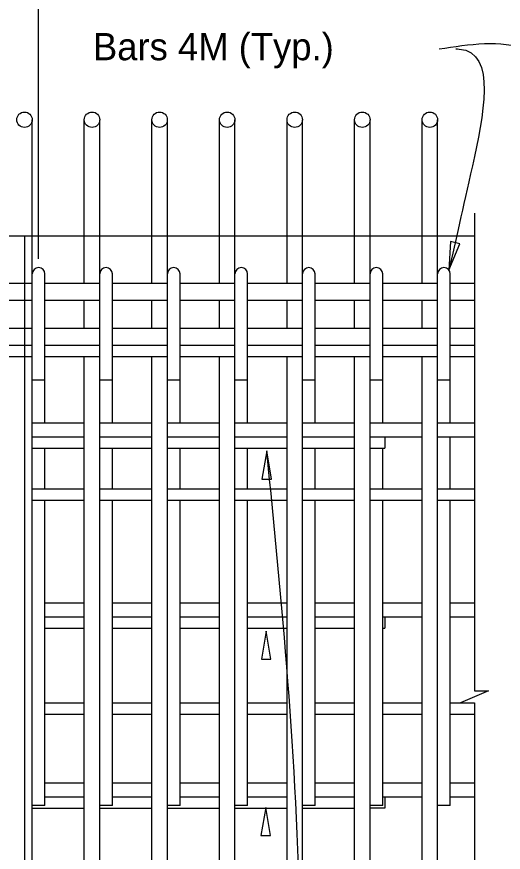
# Model space of a CAD drawing. Extents: x 120735 to 120771, y 120670.1 to 120685.4.
# Drawn here: x 120749.57 to 120751.37, y 120679.138 to 120682.233 of the extents above; entities that cross this region are included whole.
import ezdxf

# ---------------------------------------------------------------- set-up
doc = ezdxf.new("R2010")
doc.units = 0
for name, color, linetype in [('BeamConc', 7, 'Continuous'), ('BeamConc_h', 7, 'Continuous'), ('Dimension', 7, 'Continuous'), ('Rebar', 7, 'Continuous'), ('TextStructures', 7, 'Continuous')]:
    doc.layers.add(name, color=color, linetype=linetype)

msp = doc.modelspace()

# ---------------------------------------------------------------- linework, layer by layer
at = {"layer": 'BeamConc'}
msp.add_line((120747.5987, 120681.4214), (120751.2636, 120681.4214), dxfattribs=at)
at = {"layer": 'BeamConc_h'}
msp.add_line((120749.5987, 120681.4214), (120749.5987, 120677.1815), dxfattribs=at)
at = {"layer": 'Dimension'}
msp.add_line((120749.6508, 120681.3364), (120749.6508, 120682.5406), dxfattribs=at)
msp.add_lwpolyline([(120751.2636, 120681.5047), (120751.2636, 120679.7363), (120751.3153, 120679.7363), (120751.212, 120679.6913), (120751.2636, 120679.6913), (120751.2636, 120678.0689), (120751.3153, 120678.0689), (120751.212, 120678.0239), (120751.2636, 120678.0239), (120751.2636, 120676.083)], dxfattribs=at)
for points in [[(120751.1693, 120681.2943), (120751.2093, 120681.3921), (120751.1748, 120681.3998)], [(120750.4952, 120680.6245), (120750.4773, 120680.5205), (120750.5125, 120680.5204)], [(120750.4932, 120679.9578), (120750.4753, 120679.8537), (120750.5106, 120679.8536)], [(120750.4912, 120679.3042), (120750.4732, 120679.2001), (120750.5085, 120679.2)]]:
    msp.add_lwpolyline(points, close=True, dxfattribs=at)
for points in [[(120751.1329, 120682.1134), (120751.458, 120682.1121), (120751.7391, 120681.7555), (120751.672, 120681.2899)], [(120751.1944, 120682.1134), (120751.2076, 120682.1129), (120751.2559, 120681.6807), (120751.1692, 120681.2943)], [(120750.6698, 120675.9492), (120750.5712, 120675.9492), (120750.4797, 120676.5019), (120750.4952, 120680.6245)]]:
    msp.add_spline(points, degree=3, dxfattribs=at)
at = {"layer": 'Rebar'}
for p, q in [((120749.6274, 120676.3667), (120749.6274, 120681.851)), ((120749.8201, 120681.246), (120749.8201, 120681.851)), ((120749.8774, 120676.3667), (120749.8774, 120681.851)), ((120750.0701, 120681.246), (120750.0701, 120681.851)), ((120750.1274, 120676.3667), (120750.1274, 120681.851)), ((120750.3201, 120681.246), (120750.3201, 120681.851)), ((120750.3774, 120676.3667), (120750.3774, 120681.851)), ((120750.5701, 120681.246), (120750.5701, 120681.851)), ((120750.6274, 120676.3667), (120750.6274, 120681.851)), ((120750.8201, 120681.246), (120750.8201, 120681.851)), ((120750.8774, 120676.3667), (120750.8774, 120681.851)), ((120751.0701, 120681.246), (120751.0701, 120681.851)), ((120751.1274, 120676.3667), (120751.1274, 120681.851)), ((120749.6742, 120680.7287), (120749.6742, 120681.2799)), ((120749.9242, 120680.7287), (120749.9242, 120681.2799)), ((120750.1742, 120680.7287), (120750.1742, 120681.2799)), ((120750.4242, 120680.7287), (120750.4242, 120681.2799)), ((120750.6742, 120680.7287), (120750.6742, 120681.2799)), ((120750.9242, 120680.7287), (120750.9242, 120681.2799)), ((120751.1742, 120680.7287), (120751.1742, 120681.2799)), ((120749.3201, 120681.246), (120749.6274, 120681.246)), ((120749.6742, 120681.246), (120749.8774, 120681.246)), ((120749.9242, 120681.246), (120750.1274, 120681.246)), ((120750.1742, 120681.246), (120750.3774, 120681.246)), ((120750.4242, 120681.246), (120750.6274, 120681.246)), ((120750.6742, 120681.246), (120750.8774, 120681.246)), ((120750.9242, 120681.246), (120751.1274, 120681.246)), ((120751.1742, 120681.246), (120751.2636, 120681.246)), ((120749.3201, 120681.1835), (120749.6274, 120681.1835)), ((120749.6742, 120681.1835), (120749.8774, 120681.1835)), ((120749.8201, 120681.0788), (120749.8201, 120681.1835)), ((120749.9242, 120681.1835), (120750.1274, 120681.1835)), ((120750.0701, 120681.0788), (120750.0701, 120681.1835)), ((120750.1742, 120681.1835), (120750.3774, 120681.1835)), ((120750.3201, 120681.0788), (120750.3201, 120681.1835)), ((120750.4242, 120681.1835), (120750.6274, 120681.1835)), ((120750.5701, 120681.0788), (120750.5701, 120681.1835)), ((120750.6742, 120681.1835), (120750.8774, 120681.1835)), ((120750.8201, 120681.0788), (120750.8201, 120681.1835)), ((120750.9242, 120681.1835), (120751.1274, 120681.1835)), ((120751.0701, 120681.0788), (120751.0701, 120681.1835)), ((120751.1742, 120681.1835), (120751.2636, 120681.1835)), ((120749.3201, 120681.0788), (120749.6274, 120681.0788)), ((120749.6742, 120681.0788), (120749.8774, 120681.0788)), ((120749.9242, 120681.0788), (120750.1274, 120681.0788)), ((120750.1742, 120681.0788), (120750.3774, 120681.0788)), ((120750.4242, 120681.0788), (120750.6274, 120681.0788)), ((120750.6742, 120681.0788), (120750.8774, 120681.0788)), ((120750.9242, 120681.0788), (120751.1274, 120681.0788)), ((120751.1742, 120681.0788), (120751.2636, 120681.0788)), ((120749.3201, 120681.0163), (120749.6274, 120681.0163)), ((120749.6742, 120681.0163), (120749.8774, 120681.0163)), ((120749.9242, 120681.0163), (120750.1274, 120681.0163)), ((120750.1742, 120681.0163), (120750.3774, 120681.0163)), ((120750.4242, 120681.0163), (120750.6274, 120681.0163)), ((120750.6742, 120681.0163), (120750.8774, 120681.0163)), ((120750.9242, 120681.0163), (120751.1274, 120681.0163)), ((120751.1742, 120681.0163), (120751.2636, 120681.0163)), ((120749.3201, 120680.9746), (120749.6274, 120680.9746)), ((120749.6742, 120680.9746), (120749.8774, 120680.9746)), ((120749.8201, 120676.3667), (120749.8201, 120680.9746)), ((120749.9242, 120680.9746), (120750.1274, 120680.9746)), ((120750.0701, 120676.3667), (120750.0701, 120680.9746)), ((120750.1742, 120680.9746), (120750.3774, 120680.9746)), ((120750.3201, 120676.3667), (120750.3201, 120680.9746)), ((120750.4242, 120680.9746), (120750.6274, 120680.9746)), ((120750.5701, 120676.3667), (120750.5701, 120680.9746)), ((120750.6742, 120680.9746), (120750.8774, 120680.9746)), ((120750.8201, 120676.3667), (120750.8201, 120680.9746)), ((120750.9242, 120680.9746), (120751.1274, 120680.9746)), ((120751.0701, 120676.3667), (120751.0701, 120680.9746)), ((120751.1742, 120680.9746), (120751.2636, 120680.9746)), ((120749.6742, 120680.887), (120749.6274, 120680.887)), ((120749.9242, 120680.887), (120749.8774, 120680.887)), ((120750.1742, 120680.887), (120750.1274, 120680.887)), ((120750.4242, 120680.887), (120750.3774, 120680.887)), ((120750.6742, 120680.887), (120750.6274, 120680.887)), ((120750.9242, 120680.887), (120750.8774, 120680.887)), ((120751.1742, 120680.887), (120751.1274, 120680.887)), ((120749.6274, 120680.7287), (120749.8201, 120680.7287)), ((120749.8774, 120680.7287), (120750.0701, 120680.7287)), ((120750.1274, 120680.7287), (120750.3201, 120680.7287)), ((120750.3774, 120680.7287), (120750.5701, 120680.7287)), ((120750.6274, 120680.7287), (120750.8201, 120680.7287)), ((120750.8774, 120680.7287), (120751.0701, 120680.7287)), ((120751.1274, 120680.7287), (120751.2636, 120680.7287)), ((120749.6274, 120680.6766), (120749.8201, 120680.6766)), ((120749.8774, 120680.6766), (120750.0701, 120680.6766)), ((120750.1274, 120680.6766), (120750.3201, 120680.6766)), ((120750.3774, 120680.6766), (120750.5701, 120680.6766)), ((120750.6274, 120680.6766), (120750.8201, 120680.6766)), ((120750.8774, 120680.6766), (120751.0701, 120680.6766)), ((120750.9321, 120680.6766), (120750.9321, 120680.6349)), ((120751.1274, 120680.6766), (120751.2636, 120680.6766)), ((120751.1742, 120680.4839), (120751.1742, 120680.6766)), ((120749.6274, 120680.6349), (120749.8201, 120680.6349)), ((120749.6742, 120680.4839), (120749.6742, 120680.6349)), ((120749.8774, 120680.6349), (120750.0701, 120680.6349)), ((120749.9242, 120680.4839), (120749.9242, 120680.6349)), ((120750.1274, 120680.6349), (120750.3201, 120680.6349)), ((120750.1742, 120680.4839), (120750.1742, 120680.6349)), ((120750.3774, 120680.6349), (120750.5701, 120680.6349)), ((120750.4242, 120680.4839), (120750.4242, 120680.6349)), ((120750.6274, 120680.6349), (120750.8201, 120680.6349)), ((120750.6742, 120680.4839), (120750.6742, 120680.6349)), ((120750.8774, 120680.6349), (120750.9321, 120680.6349)), ((120750.9242, 120680.4839), (120750.9242, 120680.6349)), ((120749.6274, 120680.4839), (120749.8201, 120680.4839)), ((120749.8774, 120680.4839), (120750.0701, 120680.4839)), ((120750.1274, 120680.4839), (120750.3201, 120680.4839)), ((120750.3774, 120680.4839), (120750.5701, 120680.4839)), ((120750.6274, 120680.4839), (120750.8201, 120680.4839)), ((120750.8774, 120680.4839), (120751.0701, 120680.4839)), ((120751.1274, 120680.4839), (120751.2636, 120680.4839)), ((120749.6274, 120680.4422), (120749.8201, 120680.4422)), ((120749.6742, 120679.3119), (120749.6742, 120680.4422)), ((120749.8774, 120680.4422), (120750.0701, 120680.4422)), ((120749.9242, 120679.3119), (120749.9242, 120680.4422)), ((120750.1274, 120680.4422), (120750.3201, 120680.4422)), ((120750.1742, 120679.3119), (120750.1742, 120680.4422)), ((120750.3774, 120680.4422), (120750.5701, 120680.4422)), ((120750.4242, 120679.3119), (120750.4242, 120680.4422)), ((120750.6274, 120680.4422), (120750.8201, 120680.4422)), ((120750.6742, 120679.3119), (120750.6742, 120680.4422)), ((120750.8774, 120680.4422), (120751.0701, 120680.4422)), ((120750.9242, 120679.3119), (120750.9242, 120680.4422)), ((120751.1274, 120680.4422), (120751.2636, 120680.4422)), ((120751.1742, 120679.3119), (120751.1742, 120680.4422)), ((120749.6742, 120680.062), (120749.8201, 120680.062)), ((120749.9242, 120680.062), (120750.0701, 120680.062)), ((120750.1742, 120680.062), (120750.3201, 120680.062)), ((120750.4242, 120680.062), (120750.5701, 120680.062)), ((120750.6742, 120680.062), (120750.8201, 120680.062)), ((120750.9242, 120680.062), (120751.0701, 120680.062)), ((120751.1742, 120680.062), (120751.2636, 120680.062)), ((120749.6742, 120680.0099), (120749.8201, 120680.0099)), ((120749.9242, 120680.0099), (120750.0701, 120680.0099)), ((120750.1742, 120680.0099), (120750.3201, 120680.0099)), ((120750.4242, 120680.0099), (120750.5701, 120680.0099)), ((120750.6742, 120680.0099), (120750.8201, 120680.0099)), ((120750.9242, 120680.0099), (120751.0701, 120680.0099)), ((120750.9321, 120680.0099), (120750.9321, 120679.9682)), ((120751.1742, 120680.0099), (120751.2636, 120680.0099)), ((120749.6742, 120679.9682), (120749.8201, 120679.9682)), ((120749.9242, 120679.9682), (120750.0701, 120679.9682)), ((120750.1742, 120679.9682), (120750.3201, 120679.9682)), ((120750.4242, 120679.9682), (120750.5701, 120679.9682)), ((120750.6742, 120679.9682), (120750.8201, 120679.9682)), ((120750.9242, 120679.9682), (120750.9321, 120679.9682)), ((120749.6742, 120679.6922), (120749.8201, 120679.6922)), ((120749.9242, 120679.6922), (120750.0701, 120679.6922)), ((120750.1742, 120679.6922), (120750.3201, 120679.6922)), ((120750.4242, 120679.6922), (120750.5701, 120679.6922)), ((120750.6742, 120679.6922), (120750.8201, 120679.6922)), ((120750.9242, 120679.6922), (120751.0701, 120679.6922)), ((120751.1742, 120679.6922), (120751.2636, 120679.6922)), ((120749.6742, 120679.6505), (120749.8201, 120679.6505)), ((120749.9242, 120679.6505), (120750.0701, 120679.6505)), ((120750.1742, 120679.6505), (120750.3201, 120679.6505)), ((120750.4242, 120679.6505), (120750.5701, 120679.6505)), ((120750.6742, 120679.6505), (120750.8201, 120679.6505)), ((120750.9242, 120679.6505), (120751.0701, 120679.6505)), ((120751.1742, 120679.6505), (120751.2636, 120679.6505)), ((120749.6742, 120679.3953), (120749.8201, 120679.3953)), ((120749.9242, 120679.3953), (120750.0701, 120679.3953)), ((120750.1742, 120679.3953), (120750.3201, 120679.3953)), ((120750.4242, 120679.3953), (120750.5701, 120679.3953)), ((120750.6742, 120679.3953), (120750.8201, 120679.3953)), ((120750.9242, 120679.3953), (120751.0701, 120679.3953)), ((120751.1742, 120679.3953), (120751.2636, 120679.3953)), ((120749.6742, 120679.3432), (120749.8201, 120679.3432)), ((120749.9242, 120679.3432), (120750.0701, 120679.3432)), ((120750.1742, 120679.3432), (120750.3201, 120679.3432)), ((120750.4242, 120679.3432), (120750.5701, 120679.3432)), ((120750.6742, 120679.3432), (120750.8201, 120679.3432)), ((120750.9242, 120679.3432), (120751.0701, 120679.3432)), ((120750.9321, 120679.3432), (120750.9321, 120679.3015)), ((120751.1742, 120679.3432), (120751.2636, 120679.3432)), ((120749.6742, 120679.3119), (120749.6274, 120679.3119)), ((120749.9242, 120679.3119), (120749.8774, 120679.3119)), ((120750.1742, 120679.3119), (120750.1274, 120679.3119)), ((120750.4242, 120679.3119), (120750.3774, 120679.3119)), ((120750.6742, 120679.3119), (120750.6274, 120679.3119)), ((120750.9242, 120679.3119), (120750.8774, 120679.3119)), ((120751.1742, 120679.3119), (120751.1274, 120679.3119)), ((120749.6274, 120679.3015), (120749.8201, 120679.3015)), ((120749.8774, 120679.3015), (120750.0701, 120679.3015)), ((120750.1274, 120679.3015), (120750.3201, 120679.3015)), ((120750.3774, 120679.3015), (120750.5701, 120679.3015)), ((120750.6274, 120679.3015), (120750.8201, 120679.3015)), ((120750.9321, 120679.3015), (120750.8774, 120679.3015))]:
    msp.add_line(p, q, dxfattribs=at)
for centre in [(120749.5987, 120681.851), (120749.8487, 120681.851), (120750.0987, 120681.851), (120750.3487, 120681.851), (120750.5987, 120681.851), (120750.8487, 120681.851), (120751.0987, 120681.851)]:
    msp.add_circle(centre, 0.0286, dxfattribs=at)
for centre in [(120749.6508, 120681.2799), (120749.9008, 120681.2799), (120750.1508, 120681.2799), (120750.4008, 120681.2799), (120750.6508, 120681.2799), (120750.9008, 120681.2799), (120751.1508, 120681.2799)]:
    msp.add_arc(centre, 0.0234, 0, 180, dxfattribs=at)

# ---------------------------------------------------------------- texts
at = {"layer": 'TextStructures'}
msp.add_text('Bars 4M (Typ.)', height=0.1008, dxfattribs=at).set_placement((120749.852, 120682.0714))

doc.saveas('drawing.dxf')
